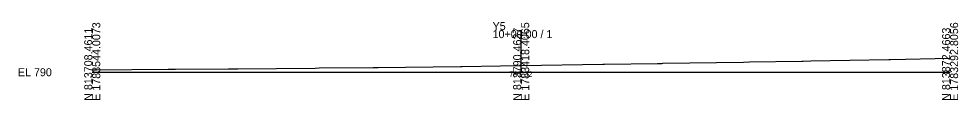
# Model space of a CAD drawing. Extents: x -26 to 1603, y -10 to 6526.
# Drawn here: x -25.7 to 302.8, y -9.7 to 17.6 of the extents above; entities that cross this region are included whole.
import ezdxf

# ---------------------------------------------------------------- set-up
doc = ezdxf.new("R2010")
doc.units = 0
for name, color, linetype in [('Exist Cross Section Cell', 7, 'Continuous'), ('Exist XS Center Line Elevation Label', 7, 'Continuous'), ('Exist XS Ground Line', 7, 'Continuous')]:
    doc.layers.add(name, color=color, linetype=linetype)

msp = doc.modelspace()

# ---------------------------------------------------------------- linework, layer by layer
at = {"layer": 'Exist Cross Section Cell'}
for p, q in [((150, 0), (150, 14.75)), ((0, 0), (150, 0)), ((150, 0), (300, 0))]:
    msp.add_line(p, q, dxfattribs=at)
at = {"layer": 'Exist XS Ground Line'}
for p, q in [((199.53, 3.12), (227.74, 3.57)), ((227.74, 3.57), (229.86, 3.6)), ((229.86, 3.6), (248.12, 3.89)), ((248.12, 3.89), (248.61, 3.9)), ((248.61, 3.9), (251.27, 3.96)), ((251.27, 3.96), (278.58, 4.5)), ((278.58, 4.5), (279.12, 4.51)), ((279.12, 4.51), (300, 4.92)), ((0, 0.85), (0.98, 0.85)), ((0.98, 0.85), (26.56, 1.05)), ((26.56, 1.05), (29.13, 1.07)), ((29.13, 1.07), (47.6, 1.21)), ((47.6, 1.21), (50.89, 1.24)), ((50.89, 1.24), (77.91, 1.47)), ((77.91, 1.47), (79.35, 1.49)), ((79.35, 1.49), (98.2, 1.65)), ((98.2, 1.65), (100.01, 1.67)), ((100.01, 1.67), (128.76, 2.05)), ((128.76, 2.05), (129.35, 2.05)), ((129.35, 2.05), (142.81, 2.23)), ((142.81, 2.23), (149.4, 2.31)), ((149.4, 2.31), (150, 2.32)), ((150, 2.32), (178.54, 2.78)), ((178.54, 2.78), (179.18, 2.79)), ((179.18, 2.79), (197.71, 3.09)), ((197.71, 3.09), (199.15, 3.11)), ((199.15, 3.11), (199.53, 3.12))]:
    msp.add_line(p, q, dxfattribs=at)

# ---------------------------------------------------------------- texts
at = {"layer": 'Exist Cross Section Cell'}
for s, p in [('E 1783544.0073', (2.8, -10)), ('E 1783418.4065', (152.8, -10)), ('E 1783292.8056', (302.8, -10)), ('N 813708.4611', (0, -10)), ('N 813790.4637', (150, -10)), ('N 813872.4663', (300, -10))]:
    msp.add_text(s, height=2.8, rotation=90, dxfattribs=at).set_placement(p)
for s, p in [('Y5', (140, 14.75)), ('10+00.00 / 1', (140, 11.95)), ('EL 790', (-26, -1.4))]:
    msp.add_text(s, height=2.8, dxfattribs=at).set_placement(p)
at = {"layer": 'Exist XS Center Line Elevation Label'}
msp.add_text('792.32', height=2, dxfattribs=at).set_placement((145.79, -1.68))

doc.saveas('drawing.dxf')
